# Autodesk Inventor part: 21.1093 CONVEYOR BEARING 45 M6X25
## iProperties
Created: 2006-02
Part Number: 21.1093 CONVEYOR BEARING 45 M6X25
Material: Steel, Mild
Description: Hex-Head Bolt
Document SubType Name: Modeling
Standard: DIN 931-1
Designer: Andy Moles
Standards Organization: DIN
Language: en-US
Size Designation: M6 x 30
Categories: <MemberInstance><Categories><Category DisplayName="Fasteners" InternalName="e4da775c-781d-43d5-af7c-5136215cf5a6" Mnemonic="FSTN"><Category DisplayName="Bolts"
Density: 1 g/cm^3
IsCustomPart: 1
Author: Andy Moles
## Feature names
1. Body [Revolution]
2. Head [Extrusion]
3. Chamfer1 [Revolution]
4. Chamfer2
